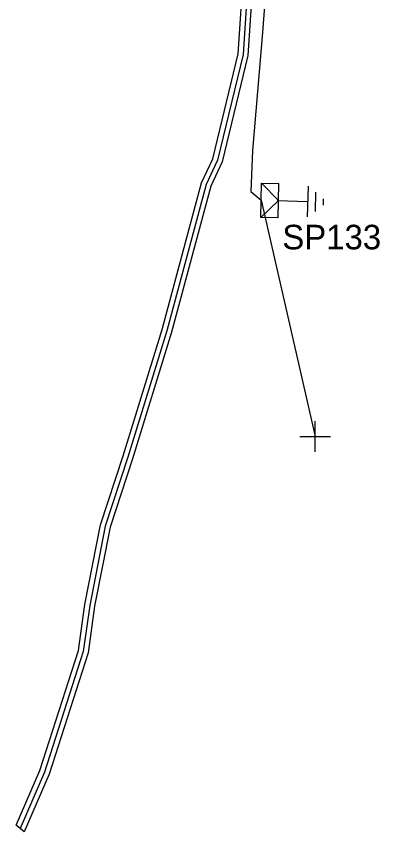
# Model space of a CAD drawing. Extents: x -717562 to -713845, y -1151196 to -1143903.
# Drawn here: x -716957.71 to -716942.94, y -1145334.17 to -1145300.99 of the extents above; entities that cross this region are included whole.
import ezdxf

# ---------------------------------------------------------------- set-up
doc = ezdxf.new("R2010")
doc.units = 0
for name, color, linetype in [('Vrstva 1', 7, 'Continuous'), ('Vrstva 14', 7, 'Continuous'), ('Vrstva 15', 7, 'Continuous'), ('Vrstva 20', 7, 'Continuous'), ('Vrstva 31', 7, 'Continuous'), ('Vrstva 33', 7, 'Continuous'), ('Vrstva 34', 7, 'Continuous'), ('Vrstva 5', 7, 'Continuous'), ('Vrstva 52', 7, 'Continuous'), ('Vrstva 59', 7, 'Continuous'), ('Vrstva 9', 7, 'Continuous')]:
    doc.layers.add(name, color=color, linetype=linetype)

# ---------------------------------------------------------------- blocks, each defined once
blk = doc.blocks.new('NN800')
at = {"layer": 'Vrstva 1'}
for points in [[(-0.442, 0.442), (0.442, -0.442)], [(-0.442, -0.442), (0.442, 0.442)]]:
    blk.add_lwpolyline(points, dxfattribs=at)
blk = doc.blocks.new('NN630')
at = {"layer": 'Vrstva 9'}
for points in [[(-0.003, -0.7), (-0.703, 0)], [(-0.703, -0.7), (-0.703, 0), (0.697, 0), (0.697, -0.7)], [(-0.003, -0.7), (0.697, 0)], [(-0.703, -0.7), (0.697, -0.7)]]:
    blk.add_lwpolyline(points, dxfattribs=at)
blk = doc.blocks.new('NN810')
at = {"layer": 'Vrstva 14'}
for points in [[(0.004, -0.64), (0.004, -1.89)], [(0.629, -1.89), (-0.621, -1.89)], [(0.388, -2.2), (-0.399, -2.2)], [(0.004, -2.515), (-0.124, -2.515)], [(0.137, -2.515), (0.004, -2.515)]]:
    blk.add_lwpolyline(points, dxfattribs=at)

msp = doc.modelspace()

# ---------------------------------------------------------------- linework, layer by layer
at = {"layer": 'Vrstva 20'}
msp.add_lwpolyline([(-716947.907, -1145296.64), (-716948.298, -1145302.579), (-716949.347, -1145306.916), (-716949.808, -1145307.898), (-716951.404, -1145313.844), (-716952.986, -1145318.989), (-716953.903, -1145321.779), (-716954.529, -1145324.992), (-716954.791, -1145326.884), (-716956.379, -1145331.819), (-716957.391, -1145334.165), (-716957.71, -1145333.894), (-716956.754, -1145331.678), (-716955.182, -1145326.794), (-716954.924, -1145324.926), (-716954.29, -1145321.678), (-716953.367, -1145318.868), (-716951.789, -1145313.734), (-716950.185, -1145307.76), (-716949.726, -1145306.782), (-716948.695, -1145302.519), (-716948.306, -1145296.618)], dxfattribs=at)
at = {"layer": 'Vrstva 5'}
msp.add_lwpolyline([(-716947.366, -1145276.463), (-716947.957, -1145277.233), (-716947.982, -1145277.913), (-716948.027, -1145279.479), (-716947.877, -1145286.399), (-716947.917, -1145290.199), (-716947.957, -1145293.309), (-716948.107, -1145296.629), (-716948.496, -1145302.549), (-716949.536, -1145306.849), (-716949.996, -1145307.829), (-716951.596, -1145313.789), (-716953.176, -1145318.929), (-716954.097, -1145321.729), (-716954.726, -1145324.959), (-716954.987, -1145326.839), (-716956.566, -1145331.749), (-716957.551, -1145334.03)], dxfattribs=at)
at = {"layer": 'Vrstva 52'}
msp.add_lwpolyline([(-716947.589, -1145276.307), (-716948.47, -1145277.33), (-716948.38, -1145277.921), (-716946.817, -1145286.609), (-716946.937, -1145289.139), (-716947.097, -1145293.439), (-716947.356, -1145296.969), (-716947.707, -1145301.649), (-716948.107, -1145306.449), (-716948.176, -1145308.119), (-716947.756, -1145308.469)], dxfattribs=at)
at = {"layer": 'Vrstva 59'}
msp.add_lwpolyline([(-716947.756, -1145308.469), (-716945.562, -1145318.084)], dxfattribs=at)

# ---------------------------------------------------------------- block references
at = {"layer": 'Vrstva 15', "rotation": 88.2265871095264}
msp.add_blockref('NN810', (-716947.756, -1145308.469), dxfattribs=at)
at = {"layer": 'Vrstva 31', "rotation": 88.77634484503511}
msp.add_blockref('NN630', (-716947.756, -1145308.469), dxfattribs=at)
at = {"layer": 'Vrstva 34', "rotation": 44.99999995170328}
msp.add_blockref('NN800', (-716945.562, -1145318.084), dxfattribs=at)

# ---------------------------------------------------------------- texts
at = {"layer": 'Vrstva 33'}
msp.add_text('SP133', height=1, dxfattribs=at).set_placement((-716946.9, -1145310.472))

doc.saveas('drawing.dxf')
